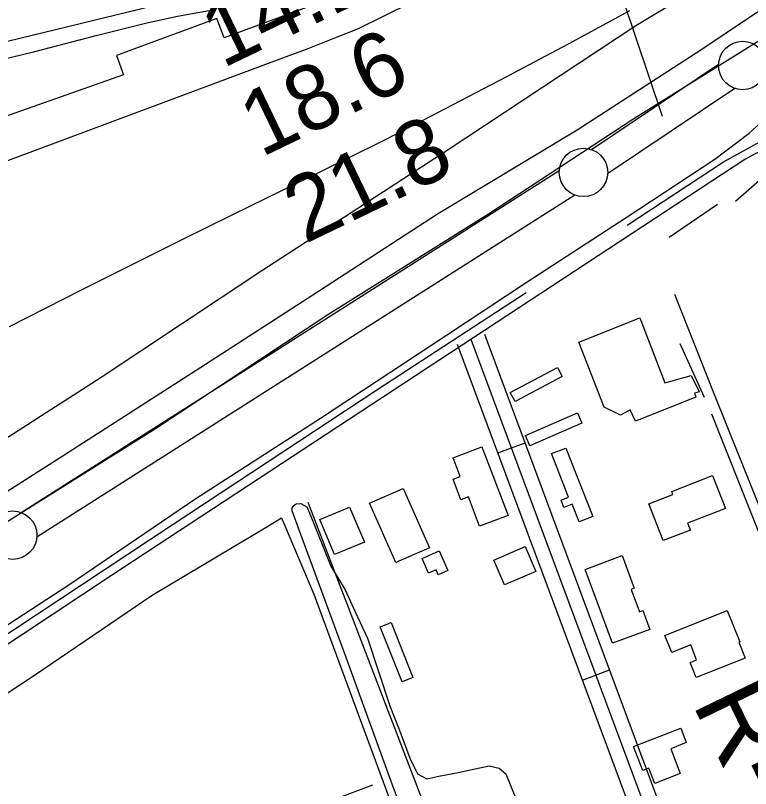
# Model space of a CAD drawing. Extents: x 3445503 to 3483459, y 540493 to 566012.
# Drawn here: x 3473551 to 3474309, y 549267 to 550065 of the extents above; entities that cross this region are included whole.
import ezdxf

# ---------------------------------------------------------------- set-up
doc = ezdxf.new("R2010")
doc.units = 0
for name, color, linetype in [('V-BLDG-OTLN', 7, 'Continuous'), ('V-DTCH-CNTR', 7, 'Continuous'), ('V-FLOD-BASE', 7, 'Continuous'), ('V-LEVE-TOET', 7, 'Continuous'), ('V-RIVR-EDGE', 7, 'Continuous'), ('V-RIVR-RANG', 7, 'Continuous'), ('V-RIVR-RANG-IDEN', 7, 'Continuous'), ('V-ROAD-CNTR', 7, 'Continuous'), ('V-RRAP-RVMT', 7, 'Continuous'), ('V-SITE-VEGE', 7, 'Continuous'), ('V-SURV-LINE', 7, 'Continuous'), ('V-TOPO-DPTH', 7, 'Continuous'), ('V-TOPO-MINR', 7, 'Continuous'), ('V-TOPO-SHOR', 7, 'Continuous')]:
    doc.layers.add(name, color=color, linetype=linetype)

msp = doc.modelspace()

# ---------------------------------------------------------------- linework, layer by layer
at = {"layer": 'V-BLDG-OTLN'}
for points in [[(3474195.14, 549752.51), (3474220.71, 549685.44), (3474247.97, 549692.99), (3474256.09, 549676.33), (3474251.47, 549674.99), (3474252.81, 549670.83), (3474190.36, 549646.13), (3474184.95, 549657.71), (3474175.21, 549652.28), (3474158.25, 549660.29), (3474132.22, 549727.36)], [(3474061.3, 549675.47), (3474109.88, 549701.2), (3474114.78, 549691.94), (3474066.2, 549666.21)], [(3474076.95, 549631.13), (3474130.57, 549654.5), (3474135.23, 549643.81), (3474081.61, 549620.43)], [(3474032.07, 549619.54), (3474059, 549548.75), (3474029.58, 549537.56), (3474018.07, 549567.84), (3474010.33, 549564.9), (3474002.24, 549586.18), (3474009.68, 549589.01), (3474002.37, 549608.25)], [(3474118.69, 549618.27), (3474146.49, 549547.58), (3474132.34, 549542.01), (3474125.11, 549560.38), (3474116.6, 549557.03), (3474113.66, 549564.52), (3474121.56, 549567.63), (3474103.93, 549612.46)], [(3474219.13, 549522.66), (3474204.31, 549560.61), (3474229.11, 549570.3), (3474227.94, 549573.28), (3474270.11, 549589.74), (3474283.28, 549556.01), (3474244.3, 549540.79), (3474247.12, 549533.6)], [(3473916.24, 549561.28), (3473950.97, 549576.59), (3473977.95, 549515.4), (3473943.22, 549500.09)], [(3473895.46, 549557.35), (3473910.76, 549521.24), (3473880.06, 549508.23), (3473864.77, 549544.34)], [(3473977.02, 549489.12), (3473970.27, 549504.39), (3473988.05, 549512.26), (3473997.01, 549492.01), (3473986.93, 549487.55), (3473984.73, 549492.53)], [(3474044.33, 549502.61), (3474076.68, 549516.55), (3474087.68, 549491.01), (3474055.33, 549477.07)], [(3474166.87, 549416.73), (3474138.62, 549493.07), (3474176.81, 549507.21), (3474189.27, 549473.55), (3474186.07, 549472.37), (3474194.64, 549449.22), (3474198.2, 549450.54), (3474205.43, 549431)], [(3474220.88, 549424.93), (3474285.21, 549450.54), (3474298.09, 549418.19), (3474297.04, 549417.77), (3474303.53, 549401.47), (3474253.21, 549381.43), (3474246.97, 549397.11), (3474253.6, 549399.75), (3474247.45, 549415.2), (3474227.86, 549407.4)], [(3473949.62, 549377.04), (3473927.19, 549433.88), (3473938.54, 549438.35), (3473960.96, 549381.52)], [(3474188.58, 549310.26), (3474237.17, 549329.12), (3474242.93, 549314.28), (3474226.81, 549308.03), (3474236.72, 549282.49), (3474210.31, 549272.24), (3474204.24, 549287.88), (3474198.18, 549285.53)]]:
    msp.add_lwpolyline(points, close=True, dxfattribs=at)
at = {"layer": 'V-DTCH-CNTR'}
for points in [[(3474987.14, 547815.78), (3474937.61, 547945.45), (3474855.21, 548162.49), (3474777.09, 548371.54), (3474695.1, 548589.76), (3474617.71, 548792.84), (3474576.23, 548893.81), (3474501.98, 549092.09), (3474410.23, 549327.9), (3474326.56, 549537.41), (3474271.54, 549674.28), (3474231.27, 549776.83)], [(3473369.55, 549253.03), (3473446.62, 549302.36), (3473570.6, 549383.96), (3473691.83, 549466.38), (3473810.18, 549536.99), (3473825.27, 549546.31)], [(3473825.27, 549546.31), (3473858.66, 549467.33), (3473953.51, 549210.41), (3474048.29, 548947.85)]]:
    msp.add_lwpolyline(points, dxfattribs=at)
at = {"layer": 'V-FLOD-BASE'}
msp.add_lwpolyline([(3475404.48, 550432.94), (3475266.03, 550348.97), (3475141.05, 550266.85), (3474992.97, 550169.15), (3474922.13, 550123.23), (3474869.62, 550092.15), (3474825.91, 550070.06), (3474787.81, 550055.83), (3474740.21, 550040.51), (3474700.19, 550031.44), (3474648.33, 550025.25), (3474582.71, 550025.93), (3474500.18, 550034.69), (3474421.65, 550048.54), (3474373.49, 550055.37), (3474364, 550055.46), (3474353.31, 550053.99), (3474345.39, 550052.49), (3474319.16, 550038.93), (3474188.65, 549958.05), (3474038.99, 549859.57), (3473873.06, 549755.73), (3473695.13, 549638.18), (3473488.21, 549508.27)], dxfattribs=at)
at = {"layer": 'V-LEVE-TOET'}
for points in [[(3473472.53, 549529.27), (3473593.1, 549605.9), (3473746.72, 549704.73), (3473857.77, 549776.33), (3473986.32, 549859.99), (3474130.33, 549946.67), (3474258.88, 550029.94), (3474309.04, 550063.42), (3474328.54, 550075.87)], [(3473482.18, 549396.46), (3473605.91, 549476.96), (3473736.82, 549566.21), (3473865.7, 549649.18), (3473994.6, 549734.11), (3474077.89, 549789.19), (3474181, 549856.27), (3474272.22, 549916.38), (3474307.95, 549943.19), (3474323.06, 549956.82)]]:
    msp.add_lwpolyline(points, dxfattribs=at)
at = {"layer": 'V-RIVR-EDGE'}
msp.add_spline([(3477967.38, 552440.81), (3477956.32, 552434.46), (3477946.92, 552428.23), (3477938.22, 552423.73), (3477929.17, 552419.58), (3477921.16, 552414.39), (3477919.42, 552411.26), (3477918.37, 552407.79), (3477915.23, 552404.32), (3477908.61, 552399.82), (3477903.74, 552398.09), (3477897.83, 552396.02), (3477895.39, 552394.29), (3477890.17, 552392.91), (3477887.39, 552391.18), (3477883.9, 552387.37), (3477874.5, 552380.44), (3477864.4, 552373.86), (3477857.09, 552370.4), (3477852.91, 552366.58), (3477848.38, 552362.77), (3477844.55, 552357.91), (3477836.89, 552356.54), (3477833.41, 552353.07), (3477830.61, 552347.17), (3477822.61, 552342.33), (3477810.07, 552333.32), (3477792.66, 552321.19), (3477781.52, 552316.7), (3477774.9, 552310.81), (3477768.98, 552306.3), (3477763.76, 552302.15), (3477759.93, 552301.46), (3477756.1, 552297.99), (3477741.12, 552286.91), (3477723.71, 552272.7), (3477708.73, 552262.3), (3477698.98, 552255.03), (3477689.59, 552251.92), (3477683.67, 552247.07), (3477677.04, 552240.48), (3477664.16, 552231.82), (3477659.28, 552227.66), (3477652.33, 552225.59), (3477646.06, 552221.44), (3477633.17, 552211.04), (3477593.46, 552180.55), (3477582.32, 552173.27), (3477570.13, 552164.61), (3477532.87, 552138.29), (3477506.06, 552118.54), (3477500.14, 552114.38), (3477492.82, 552109.88), (3477485.86, 552105.03), (3477479.95, 552105.04), (3477473.69, 552102.97), (3477446.18, 552084.62), (3477429.46, 552072.84), (3477413.1, 552061.41), (3477403.34, 552054.13), (3477399.86, 552052.75), (3477395.34, 552051.02), (3477385.95, 552047.57), (3477366.11, 552036.84), (3477295.43, 551995.3), (3477256.09, 551969.67), (3477245.99, 551964.14), (3477236.59, 551956.16), (3477232.41, 551952.7), (3477223.36, 551948.9), (3477210.83, 551941.98), (3477195.51, 551933.32), (3477189.24, 551928.12), (3477182.28, 551923.62), (3477175.66, 551921.2), (3477171.84, 551919.48), (3477168.35, 551916.01), (3477159.65, 551911.51), (3477143.63, 551901.12), (3477124.48, 551889.7), (3477117.87, 551886.24), (3477112.31, 551885.21), (3477107.43, 551883.13), (3477100.82, 551879.67), (3477094.55, 551874.82), (3477091.41, 551870.66), (3477085.15, 551867.55), (3477074.35, 551860.97), (3477058.34, 551853.01), (3477036.06, 551840.2), (3477024.57, 551831.54), (3477014.13, 551825.31), (3477007.52, 551823.24), (3476990.81, 551813.9), (3476960.86, 551794.5), (3476943.45, 551781.68), (3476927.78, 551771.99), (3476905.5, 551758.83), (3476879.04, 551741.86), (3476864.07, 551733.91), (3476854.32, 551727.33), (3476848.05, 551722.82), (3476839.7, 551719.71), (3476833.44, 551719.03), (3476830.31, 551718.35), (3476827.17, 551714.18), (3476822.99, 551711.41), (3476800.37, 551700.34), (3476764.18, 551684.79), (3476719.29, 551666.82), (3476694.59, 551658.19), (3476687.27, 551653), (3476681.71, 551651.62), (3476674.75, 551649.9), (3476665.71, 551648.53), (3476648.67, 551645.79), (3476639.28, 551643.73), (3476627.45, 551639.94), (3476617.01, 551635.44), (3476607.26, 551630.25), (3476595.08, 551624.37), (3476590.56, 551623.34), (3476578.39, 551623.37), (3476574.57, 551622.68), (3476569.69, 551620.61), (3476563.77, 551616.45), (3476559.6, 551613.34), (3476542.56, 551610.94), (3476516.47, 551605.45), (3476500.81, 551600.62), (3476493.86, 551600.29), (3476490.38, 551599.6), (3476484.82, 551597.88), (3476475.77, 551594.77), (3476466.71, 551587.84), (3476459.75, 551583.34), (3476454.18, 551581.61), (3476446.52, 551576.77), (3476440.26, 551571.91), (3476435.03, 551568.1), (3476422.85, 551564.31), (3476402.31, 551551.5), (3476381.42, 551537.64), (3476372.02, 551531.76), (3476359.83, 551524.14), (3476350.77, 551515.47), (3476342.07, 551510.63), (3476327.1, 551501.97), (3476312.48, 551494.01), (3476294.03, 551482.24), (3476278.36, 551473.59), (3476258.52, 551460.43), (3476247.72, 551451.76), (3476240.75, 551444.83), (3476231.34, 551437.9), (3476220.55, 551432.01), (3476209.41, 551425.09), (3476201.75, 551420.24), (3476188.86, 551409.5), (3476180.85, 551401.87), (3476169.01, 551395.29), (3476157.87, 551386.28), (3476151.59, 551379.69), (3476140.81, 551375.2), (3476129.66, 551366.54), (3476121.64, 551357.17), (3476113.97, 551349.54), (3476103.18, 551342.96), (3476089.96, 551336.74), (3476064.21, 551328.81), (3476038.81, 551317.75), (3476021.05, 551308.06), (3476001.91, 551296.28), (3475987.97, 551285.89), (3475980.31, 551280), (3475968.83, 551275.51), (3475961.87, 551272.74), (3475958.38, 551268.23), (3475953.5, 551261.29), (3475933.66, 551252.65), (3475913.82, 551241.92), (3475899.54, 551232.57), (3475888.4, 551224.26), (3475872.03, 551212.13), (3475859.14, 551202.43), (3475843.82, 551192.04), (3475828.85, 551182.69), (3475807.62, 551170.92), (3475790.9, 551159.84), (3475778.36, 551148.4), (3475750.85, 551127.61), (3475732.39, 551113.75), (3475710.11, 551101.64), (3475688.52, 551089.18), (3475657.55, 551073.26), (3475627.61, 551057.69), (3475610.21, 551048), (3475592.8, 551039.35), (3475578.88, 551033.83), (3475567.76, 551033.16), (3475559.41, 551030.74), (3475547.22, 551022.78), (3475531.19, 551007.87), (3475514.13, 550995.05), (3475489.76, 550979.81), (3475462.25, 550961.81), (3475436.83, 550945.88), (3475412.11, 550930.3), (3475404.1, 550924.75), (3475394.36, 550919.91), (3475383.57, 550914.03), (3475369.99, 550906.41), (3475361.28, 550899.48), (3475348.76, 550895.34), (3475341.1, 550891.54), (3475331.35, 550883.91), (3475319.51, 550875.25), (3475304.18, 550864.51), (3475282.26, 550854.49), (3475261.03, 550843.76), (3475243.97, 550835.81), (3475209.51, 550818.51), (3475176.09, 550796), (3475149.62, 550777.64), (3475114.79, 550750.61), (3475097.38, 550737.79), (3475087.61, 550726.34), (3475078.2, 550715.94), (3475072.97, 550709), (3475070.53, 550706.57), (3475067.05, 550705.54), (3475062.18, 550704.16), (3475055.22, 550700.35), (3475048.25, 550694.46), (3475043.37, 550686.47), (3475033.26, 550677.81), (3475023.51, 550668.1), (3475018.97, 550662.55), (3475016.53, 550657.69), (3475015.13, 550654.21), (3475012.34, 550650.75), (3475004.68, 550644.85), (3475000.49, 550640), (3474998.05, 550636.53), (3474987.95, 550627.17), (3474974.7, 550613.64), (3474958.33, 550599.43), (3474946.49, 550590.77), (3474937.43, 550583.49), (3474926.29, 550574.48), (3474912.7, 550563.39), (3474895.64, 550553.35), (3474877.89, 550543.31), (3474859.78, 550532.23), (3474849.69, 550527.04), (3474846.2, 550523.23), (3474838.55, 550519.42), (3474826.02, 550512.85), (3474803.4, 550503.52), (3474763.73, 550488.32), (3474757.46, 550484.51), (3474754.33, 550483.13), (3474743.2, 550479.33), (3474732.06, 550474.49), (3474701.44, 550462.4), (3474681.26, 550456.19), (3474669.43, 550452.05), (3474656.21, 550445.83), (3474651.33, 550441.67), (3474649.58, 550437.85), (3474646.43, 550428.47), (3474639.47, 550427.79), (3474629.04, 550425.04), (3474622.08, 550424.36), (3474617.22, 550424.37), (3474614.08, 550422.64), (3474611.3, 550419.87), (3474606.42, 550417.1), (3474599.82, 550416.77), (3474592.51, 550415.05), (3474584.16, 550412.63), (3474580.68, 550409.86), (3474579.98, 550407.08), (3474579.27, 550402.22), (3474577.52, 550398.74), (3474572.3, 550395.28), (3474569.53, 550397.72), (3474568.84, 550399.46), (3474566.4, 550398.42), (3474565, 550396.34), (3474560.83, 550396.35), (3474558.05, 550394.62), (3474557.35, 550393.93), (3474552.82, 550390.46), (3474550.03, 550386.3), (3474547.24, 550382.48), (3474544.46, 550381.1), (3474541.68, 550382.49), (3474539.94, 550382.15), (3474539.24, 550379.72), (3474537.48, 550373.47), (3474536.43, 550368.95), (3474533.64, 550364.79), (3474528.77, 550363.06), (3474524.94, 550362.72), (3474521.13, 550367.25), (3474518.35, 550367.95), (3474514.87, 550365.87), (3474513.47, 550363.79), (3474515.54, 550355.79), (3474514.14, 550350.93), (3474510.65, 550345.03), (3474504.72, 550337.39), (3474501.59, 550337.05), (3474494.98, 550337.07), (3474490.12, 550336.73), (3474486.29, 550336.74), (3474483.5, 550334.67), (3474481.76, 550332.58), (3474479.67, 550329.46), (3474476.19, 550328.08), (3474468.89, 550327.05), (3474462.63, 550327.42), (3474450.81, 550326.75), (3474441.42, 550325.73), (3474433.07, 550323.32), (3474424.37, 550320.56), (3474416.37, 550316.75), (3474412.18, 550311.55), (3474406.96, 550307.39), (3474397.21, 550301.85), (3474392, 550301.52), (3474386.09, 550302.58), (3474381.57, 550303.28), (3474374.97, 550303.3), (3474367.31, 550301.23), (3474361.4, 550298.47), (3474352.69, 550292.93), (3474347.12, 550290.85), (3474344.69, 550291.9), (3474343.66, 550293.64), (3474340.87, 550293.65), (3474339.48, 550290.18), (3474332.17, 550288.8), (3474327.3, 550287.43), (3474316.87, 550285.71), (3474310.61, 550284.69), (3474304.35, 550286.09), (3474293.23, 550286.12), (3474261.93, 550282.03), (3474232.37, 550274.1), (3474219.84, 550269.96), (3474206.62, 550267.56), (3474200.71, 550264.8), (3474193.4, 550260.99), (3474172.52, 550254.09), (3474156.87, 550248.91), (3474145.38, 550244.77), (3474138.08, 550243.05), (3474131.48, 550243.07), (3474123.82, 550240.65), (3474116.86, 550237.89), (3474100.52, 550235.15), (3474090.09, 550234.82), (3474081.39, 550233.8), (3474068.17, 550230.01), (3474051.48, 550225.53), (3474039.3, 550220), (3474031.3, 550218.98), (3474029.56, 550217.59), (3474028.85, 550213.42), (3474027.11, 550213.77), (3474025.04, 550217.6), (3474021.91, 550218.31), (3474017.04, 550215.54), (3474014.6, 550214.85), (3474009.39, 550215.21), (3474003.13, 550213.49), (3473996.17, 550213.5), (3473986.44, 550212.83), (3473971.48, 550209.39), (3473947.82, 550201.11), (3473928, 550196.99), (3473915.48, 550196.67), (3473910.96, 550195.29), (3473900.52, 550191.14), (3473896.34, 550188.03), (3473890.08, 550187.69), (3473880.69, 550185.98), (3473877.56, 550183.9), (3473876.16, 550180.78), (3473870.94, 550177.66), (3473863.29, 550176.29), (3473852.85, 550174.23), (3473846.58, 550170.07), (3473843.45, 550166.6), (3473829.89, 550165.94), (3473817.36, 550162.5), (3473797.2, 550162.89), (3473790.94, 550160.48), (3473774.24, 550153.56), (3473761.37, 550150.47), (3473751.28, 550148.75), (3473741.55, 550149.13), (3473732.16, 550148.45), (3473721.73, 550147.78), (3473708.51, 550145.38), (3473703.99, 550142.27), (3473699.8, 550137.76), (3473693.19, 550136.04), (3473684.5, 550136.06), (3473676.51, 550136.77), (3473667.81, 550135.06), (3473650.41, 550127.45), (3473634.41, 550121.23), (3473613.53, 550111.55), (3473599.6, 550103.24), (3473599.59, 550100.81), (3473599.58, 550095.59), (3473597.49, 550095.25), (3473595.76, 550095.26), (3473589.51, 550099.79), (3473582.56, 550101.89), (3473571.09, 550100.18), (3473560.3, 550096.73), (3473548.81, 550088.07), (3473541.49, 550082.18), (3473536.97, 550079.76), (3473530.71, 550079.08), (3473522.38, 550084.31), (3473518.56, 550085.71), (3473509.87, 550085.39), (3473487.61, 550081.62), (3473463.96, 550077.16), (3473450.75, 550076.15), (3473424.33, 550076.56), (3473415.29, 550076.93), (3473413.2, 550075.2), (3473411.11, 550073.12), (3473410.04, 550064.08), (3473387.1, 550062.05), (3473385.36, 550062.06), (3473385.03, 550070.05), (3473384.34, 550071.1), (3473381.21, 550072.15), (3473364.17, 550070.45), (3473359.3, 550067.68), (3473346.09, 550067.72), (3473344.35, 550066.33), (3473345.02, 550059.03), (3473343.63, 550057.64), (3473340.51, 550060.08), (3473338.08, 550063.91), (3473333.22, 550063.58), (3473315.82, 550059.45), (3473309.91, 550055.99), (3473306.77, 550053.21), (3473302.25, 550053.57), (3473296.7, 550055.67), (3473292.87, 550055.68), (3473289.74, 550052.56), (3473286.6, 550050.48), (3473283.13, 550051.88), (3473279.31, 550052.93), (3473267.48, 550050.53)], degree=3, dxfattribs=at)
at = {"layer": 'V-RIVR-RANG'}
msp.add_line((3474218.53, 549960.37), (3473951.21, 550756.71), dxfattribs=at)
at = {"layer": 'V-ROAD-CNTR'}
for p, q in [((3474048.48, 549613.13), (3474076.59, 549623.6)), ((3474135.71, 549378.85), (3474163.82, 549389.31))]:
    msp.add_line(p, q, dxfattribs=at)
for points in [[(3474303.42, 549915.84), (3473650, 549486.76), (3473343.58, 549283.81)], [(3474972.04, 547235.99), (3474627.34, 548167.6), (3474233.58, 549201.96), (3474034.92, 549735.53)], [(3474864.24, 547440.89), (3474599.26, 548157.06), (3474205.51, 549191.39), (3474006.8, 549725.06)], [(3474957.98, 547230.79), (3474613.3, 548162.33), (3474219.54, 549196.67), (3474020.86, 549730.3)], [(3473329.61, 549070.24), (3473342.51, 549064.63), (3473354.42, 549063.83), (3473367.57, 549064), (3473382.15, 549064.41), (3473401.26, 549069.14), (3473547.92, 549131.4), (3473599.57, 549150.21), (3473919.43, 549270.55)]]:
    msp.add_lwpolyline(points, dxfattribs=at)
msp.add_arc((3474432.12, 549703.19), 248.56, 77.17767, 121.18266, dxfattribs=at)
at = {"layer": 'V-RRAP-RVMT'}
for p, q in [((3473885.54, 550085.68), (3473765.99, 550041.41)), ((3473758.48, 550061.51), (3473655.11, 550023.15)), ((3473765.99, 550041.41), (3473758.48, 550061.51)), ((3473655.11, 550023.15), (3473662.16, 550003.2)), ((3473662.16, 550003.2), (3473538.36, 549959.76))]:
    msp.add_line(p, q, dxfattribs=at)
at = {"layer": 'V-SITE-VEGE'}
for points in [[(3474779.35, 550132.41), (3474737.45, 550117.83), (3474682.8, 550106.89), (3474613.57, 550101.42), (3474584.42, 550103.25), (3474557.09, 550105.07), (3474511.55, 550110.54), (3474458.72, 550123.3), (3474418.64, 550136.06), (3474371.27, 550141.53), (3474323.9, 550128.77), (3474269.25, 550101.43), (3474190.91, 550054.03), (3473996.09, 549925.21)], [(3473502.29, 550011), (3473569.29, 550026.92), (3473633.92, 550044.04), (3473686.25, 550056.95), (3473717.95, 550063.74), (3473750.83, 550069.72)], [(3473996.09, 549925.21), (3473804.91, 549801.12), (3473639.09, 549690.94), (3473491.56, 549596.33)], [(3474017.38, 549066.89), (3473940.71, 549267.54), (3473891.91, 549402.27), (3473845.09, 549528.93), (3473836.14, 549553.42), (3473836.4, 549556.65), (3473837.34, 549558.25), (3473839.43, 549559.84), (3473840.81, 549560.51), (3473845.19, 549561.16), (3473851.38, 549557.64), (3473856.09, 549546.31), (3473876.07, 549496.37), (3473891.01, 549471.81), (3473901.14, 549449.15), (3473913.98, 549422.07), (3473937.21, 549352.07), (3473948.42, 549323.4), (3473957.6, 549298.21), (3473965.49, 549282.02), (3473975.11, 549276.85), (3473987.57, 549279.49), (3474005.8, 549282.98), (3474039.71, 549290.23), (3474049.82, 549288.05), (3474056.9, 549281.99), (3474096.86, 549182.81)]]:
    msp.add_lwpolyline(points, dxfattribs=at)
at = {"layer": 'V-SURV-LINE'}
for points in [[(3474145.05, 549926.23), (3474276.23, 550014.29)], [(3474145.05, 549926.23), (3474276.23, 550014.29)], [(3474292.94, 549989.38), (3474161.76, 549901.31)], [(3474292.94, 549989.38), (3474161.76, 549901.31)], [(3473556.83, 549551.74), (3474111.9, 549904.57)], [(3473556.83, 549551.74), (3474111.9, 549904.57)], [(3474128, 549879.25), (3473572.92, 549526.42)], [(3474128, 549879.25), (3473572.92, 549526.42)]]:
    msp.add_lwpolyline(points, dxfattribs=at)
for centre in [(3474301.17, 550012.97), (3474136.82, 549902.63), (3473548.01, 549528.36)]:
    msp.add_circle(centre, 25, dxfattribs=at)
at = {"layer": 'V-TOPO-DPTH'}
msp.add_lwpolyline([(3472799.28, 549857.36), (3473865.35, 550116.97), (3473885.73, 550123.56), (3473892.41, 550125.76), (3474613.69, 550422.76), (3474630.35, 550431.77), (3474646.8, 550441.16), (3474663.11, 550450.8), (3474956.95, 550628.97), (3475008.58, 550660.26), (3475060.22, 550691.53), (3475111.87, 550722.79), (3475163.54, 550754.03), (3475251.52, 550807.21), (3475259.2, 550811.84), (3475266.9, 550816.45), (3475274.6, 550821.05), (3475282.32, 550825.63), (3475333.59, 550855.96), (3475366.94, 550875.72), (3475400.26, 550895.52)], dxfattribs=at)
at = {"layer": 'V-TOPO-MINR'}
for points in [[(3473218.35, 549793.87), (3473826.79, 550020.71), (3473852.82, 550030.58), (3473878.77, 550040.65), (3473904.6, 550051), (3474667.47, 550428.2), (3474693.2, 550443.74), (3475222.21, 550771.84), (3475230.97, 550777.26), (3475239.74, 550782.67), (3475248.51, 550788.08), (3475257.3, 550793.47), (3475272.05, 550802.5), (3475273.46, 550803.36), (3475276.3, 550805.07), (3475277.73, 550805.91), (3475286.88, 550811.29), (3475292.89, 550814.82), (3475298.89, 550818.35), (3475822.95, 551127.5)], [(3472799.28, 549857.36), (3473865.35, 550116.97), (3473885.73, 550123.56), (3473892.41, 550125.76), (3474613.69, 550422.76), (3474630.35, 550431.77), (3474646.8, 550441.16), (3474663.11, 550450.8), (3474956.95, 550628.97), (3475008.58, 550660.26), (3475060.22, 550691.53), (3475111.87, 550722.79), (3475163.54, 550754.03), (3475251.52, 550807.21), (3475259.2, 550811.84), (3475266.9, 550816.45), (3475274.6, 550821.05), (3475282.32, 550825.63), (3475333.59, 550855.96), (3475366.94, 550875.72), (3475400.26, 550895.52)], [(3473544.7, 549743.75), (3473619.54, 549781.72), (3473671.06, 549807.69), (3473722.66, 549833.48), (3473774.41, 549859), (3473826.24, 549884.33), (3473864.53, 549902.93), (3473897.21, 549918.98), (3473929.79, 549935.22), (3473962.23, 549951.75), (3473994.56, 549968.48), (3474057.72, 550001.5), (3474121.33, 550035.29), (3474184.64, 550069.63)]]:
    msp.add_lwpolyline(points, dxfattribs=at)
at = {"layer": 'V-TOPO-SHOR'}
for p, q in [((3474225.29, 549835.75), (3474275.01, 549869.93)), ((3474236.25, 549726.16), (3474261.33, 549670.65)), ((3473852.36, 549562.27), (3474076.12, 548981.12))]:
    msp.add_line(p, q, dxfattribs=at)
for points in [[(3474181.78, 549848.18), (3474281.23, 549913.44), (3474343.38, 549947.62), (3474386.89, 549960.05), (3474421.08, 549966.27), (3474492.55, 549956.95), (3474601.32, 549932.09), (3474700.77, 549907.22), (3474756.71, 549907.22), (3474806.43, 549913.44), (3474853.05, 549935.19), (3474971.14, 550003.56), (3475030.19, 550043.96)], [(3474293.66, 549873.04), (3474318.52, 549894.79), (3474343.38, 549907.22), (3474380.68, 549922.76), (3474424.18, 549928.98)], [(3474077.83, 549778.23), (3473923.8, 549677.83), (3473713.63, 549539.26), (3473524.95, 549414.7), (3473344.21, 549293.22), (3473271.38, 549245.74), (3473241.92, 549226.28), (3473222.06, 549217), (3473177.2, 549199.28), (3473082.03, 549171.4)], [(3474269.04, 549653.59), (3474357.51, 549430.48), (3474431.33, 549241.06), (3474508.98, 549039.76), (3474559.67, 548903.87)]]:
    msp.add_lwpolyline(points, dxfattribs=at)

# ---------------------------------------------------------------- texts
at = {"layer": 'V-RIVR-RANG'}
for s, p in [('14.1', (3473764.4, 550009.61)), ('18.6', (3473804.2, 549917.79)), ('21.8', (3473849.47, 549828.6))]:
    msp.add_text(s, height=67, rotation=25.70833, dxfattribs=at).set_placement(p)
at = {"layer": 'V-RIVR-RANG-IDEN'}
msp.add_text('R-149.8', height=83, rotation=295.8501, dxfattribs=at).set_placement((3474248.46, 549355.29))

doc.saveas('drawing.dxf')
